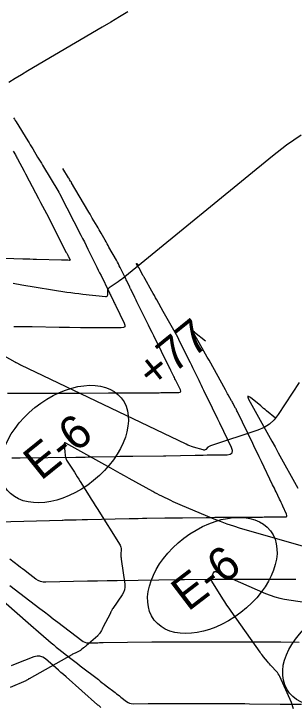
# Model space of a CAD drawing. Extents: x 1005228 to 1008882, y 1883389 to 1885754.
# Drawn here: x 1008004.6 to 1008057, y 1884530.7 to 1884660.1 of the extents above; entities that cross this region are included whole.
import ezdxf

# ---------------------------------------------------------------- set-up
doc = ezdxf.new("R2010")
doc.units = 0
for name, color, linetype in [('ATDIMS', 7, 'Continuous'), ('C-ANNO-NOTE', 7, 'Continuous'), ('R_Erosion', 7, 'Continuous'), ('S_BASELINE', 7, 'Continuous'), ('S_BRIDGE', 7, 'Continuous'), ('TSOBSTACLE', 7, 'Continuous')]:
    doc.layers.add(name, color=color, linetype=linetype)

msp = doc.modelspace()

# ---------------------------------------------------------------- linework, layer by layer
at = {"layer": 'ATDIMS'}
msp.add_lwpolyline([(1008001.59, 1884565.28), (1008013.61, 1884565.59), (1008013.83, 1884565.59), (1008014.05, 1884565.6), (1008014.27, 1884565.6), (1008014.49, 1884565.61), (1008015.36, 1884565.63), (1008015.58, 1884565.63), (1008015.79, 1884565.64), (1008016.01, 1884565.64), (1008016.23, 1884565.65), (1008017.35, 1884565.67), (1008017.61, 1884565.67), (1008017.87, 1884565.68), (1008018.13, 1884565.68), (1008018.39, 1884565.69), (1008026.17, 1884565.86), (1008027, 1884565.87), (1008027.83, 1884565.89), (1008028.66, 1884565.91), (1008029.49, 1884565.92), (1008032.81, 1884565.98), (1008033.63, 1884565.99), (1008034.46, 1884566.01), (1008035.29, 1884566.02), (1008036.12, 1884566.03), (1008040.57, 1884566.08), (1008041.1, 1884566.08), (1008041.63, 1884566.09), (1008042.16, 1884566.1), (1008042.68, 1884566.1), (1008044.79, 1884566.12), (1008045.32, 1884566.13), (1008045.85, 1884566.13), (1008046.38, 1884566.14), (1008046.9, 1884566.14), (1008050.49, 1884566.15), (1008050.8, 1884566.15), (1008051.11, 1884566.15), (1008051.43, 1884566.16), (1008051.74, 1884566.16), (1008053.04, 1884566.16), (1008053.32, 1884566.16), (1008053.6, 1884566.16), (1008053.88, 1884566.16), (1008054.15, 1884566.16), (1008055.26, 1884566.16), (1008055.49, 1884566.19), (1008055.62, 1884566.28), (1008055.66, 1884566.44), (1008055.59, 1884566.66), (1008054.92, 1884568.17), (1008054.76, 1884568.51), (1008054.61, 1884568.84), (1008054.45, 1884569.18), (1008054.29, 1884569.51), (1008053.64, 1884570.86), (1008053.48, 1884571.19), (1008053.32, 1884571.53), (1008053.15, 1884571.86), (1008052.99, 1884572.19), (1008050.89, 1884576.53), (1008050.49, 1884577.37), (1008050.09, 1884578.2), (1008049.68, 1884579.03), (1008049.28, 1884579.87), (1008046.4, 1884585.82), (1008046.32, 1884585.99), (1008046.23, 1884586.17), (1008046.14, 1884586.34), (1008046.04, 1884586.51), (1008045.67, 1884587.19), (1008045.58, 1884587.36), (1008045.48, 1884587.53), (1008045.39, 1884587.7), (1008045.29, 1884587.87), (1008044.7, 1884588.94), (1008044.57, 1884589.17), (1008044.44, 1884589.41), (1008044.31, 1884589.64), (1008044.18, 1884589.88), (1008041.09, 1884595.44), (1008040.77, 1884596), (1008040.46, 1884596.57), (1008040.14, 1884597.13), (1008039.82, 1884597.7), (1008037.97, 1884600.98), (1008037.95, 1884601.02), (1008037.95, 1884601.04), (1008037.96, 1884601.03), (1008038, 1884601.01), (1008038.2, 1884600.85), (1008038.3, 1884600.77), (1008038.39, 1884600.69), (1008040.42, 1884599.03)], dxfattribs=at)
at = {"layer": 'C-ANNO-NOTE'}
for points in [[(1008025.94, 1884660.48), (1008024.33, 1884659.53), (1008022.72, 1884658.58), (1008021.11, 1884657.63), (1008007.2, 1884649.44), (1008006.01, 1884648.73), (1008004.82, 1884648.02), (1008003.64, 1884647.29)], [(1008058.3, 1884637.44), (1008055.58, 1884635.56), (1008052.96, 1884633.54), (1008025.37, 1884611.02), (1008025.06, 1884610.77), (1008024.74, 1884610.53), (1008024.42, 1884610.3), (1008024.1, 1884610.07), (1008022.44, 1884608.93), (1008022.3, 1884608.81), (1008022.2, 1884608.68), (1008022.14, 1884608.52), (1008022.12, 1884608.34), (1008022.09, 1884607.59), (1008022.06, 1884607.43), (1008021.99, 1884607.32), (1008021.87, 1884607.26), (1008021.71, 1884607.26), (1008017.53, 1884607.71), (1008016.78, 1884607.8), (1008016.02, 1884607.9), (1008015.27, 1884608), (1008014.51, 1884608.11), (1008006.09, 1884609.43), (1008004.45, 1884609.75)], [(1008057.96, 1884591.26), (1008054.03, 1884585.3), (1008053.27, 1884584.33), (1008052.39, 1884583.52), (1008051.38, 1884582.88), (1008050.24, 1884582.4), (1008041.36, 1884579.46), (1008041.23, 1884579.41), (1008041.11, 1884579.34), (1008040.99, 1884579.26), (1008040.89, 1884579.17), (1008040.48, 1884578.79), (1008040.37, 1884578.71), (1008040.25, 1884578.66), (1008040.13, 1884578.65), (1008040, 1884578.67), (1008038.18, 1884579.21), (1008037.83, 1884579.32), (1008037.49, 1884579.45), (1008037.16, 1884579.58), (1008036.83, 1884579.73), (1008005.93, 1884594.49), (1008005.9, 1884594.51), (1008005.87, 1884594.53), (1008005.83, 1884594.54), (1008005.8, 1884594.56), (1008005.63, 1884594.65), (1008005.62, 1884594.66), (1008005.61, 1884594.67), (1008005.6, 1884594.68), (1008005.58, 1884594.68), (1008005.48, 1884594.74), (1008005.12, 1884594.93), (1008005.05, 1884594.96), (1008004.99, 1884595), (1008004.93, 1884595.03), (1008004.86, 1884595.07), (1007990.38, 1884603.18)], [(1008061.61, 1884559.84), (1008046.98, 1884564.04), (1008045.73, 1884564.42), (1008044.49, 1884564.84), (1008043.26, 1884565.29), (1008042.05, 1884565.77), (1008035.67, 1884568.43), (1008035.24, 1884568.62), (1008034.81, 1884568.81), (1008034.38, 1884569.01), (1008033.95, 1884569.21), (1008032.25, 1884570.03), (1008031.83, 1884570.24), (1008031.41, 1884570.46), (1008030.99, 1884570.68), (1008030.58, 1884570.9), (1008026.19, 1884573.34), (1008025.32, 1884573.82), (1008024.45, 1884574.3), (1008023.58, 1884574.79), (1008022.71, 1884575.27), (1008014.29, 1884579.95), (1008014.17, 1884580), (1008014.08, 1884579.98), (1008014.03, 1884579.91), (1008014.03, 1884579.78), (1008014.08, 1884579.11), (1008014.09, 1884578.95), (1008014.1, 1884578.78), (1008014.12, 1884578.62), (1008014.13, 1884578.45), (1008014.21, 1884577.55), (1008014.24, 1884577.35), (1008014.3, 1884577.15), (1008014.37, 1884576.97), (1008014.47, 1884576.79), (1008015.91, 1884574.53), (1008016.18, 1884574.09), (1008016.46, 1884573.66), (1008016.73, 1884573.22), (1008017.01, 1884572.79), (1008018.71, 1884570.11), (1008019.08, 1884569.52), (1008019.46, 1884568.93), (1008019.83, 1884568.33), (1008020.2, 1884567.74), (1008024.45, 1884560.91), (1008024.55, 1884560.72), (1008024.62, 1884560.51), (1008024.66, 1884560.3), (1008024.66, 1884560.09), (1008024.63, 1884559.19), (1008024.62, 1884558.97), (1008024.63, 1884558.75), (1008024.65, 1884558.53), (1008024.67, 1884558.31), (1008025.33, 1884553.6), (1008025.36, 1884553.07), (1008025.29, 1884552.57), (1008025.13, 1884552.08), (1008024.86, 1884551.62), (1008023.1, 1884549.06), (1008023.05, 1884549), (1008023.01, 1884548.93), (1008022.97, 1884548.86), (1008022.94, 1884548.79), (1008022.8, 1884548.51), (1008022.76, 1884548.44), (1008022.73, 1884548.37), (1008022.69, 1884548.3), (1008022.66, 1884548.23), (1008021.25, 1884545.51), (1008021.18, 1884545.37), (1008021.11, 1884545.24), (1008021.04, 1884545.11), (1008020.96, 1884544.97), (1008020.66, 1884544.45), (1008020.58, 1884544.32), (1008020.49, 1884544.2), (1008020.39, 1884544.09), (1008020.28, 1884543.98), (1008018.1, 1884542.09), (1008017.99, 1884542), (1008017.87, 1884541.9), (1008017.76, 1884541.81), (1008017.64, 1884541.71), (1008017.18, 1884541.34), (1008017.06, 1884541.25), (1008016.94, 1884541.16), (1008016.81, 1884541.09), (1008016.68, 1884541.03), (1008016.04, 1884540.74), (1008015.89, 1884540.67), (1008015.74, 1884540.6), (1008015.59, 1884540.52), (1008015.44, 1884540.44), (1008007.48, 1884535.97), (1008007.43, 1884535.94), (1008007.37, 1884535.91), (1008007.31, 1884535.87), (1008007.26, 1884535.84), (1008006.92, 1884535.63), (1008006.91, 1884535.63), (1008006.89, 1884535.62), (1008006.88, 1884535.61), (1008006.88, 1884535.61), (1008006.84, 1884535.59), (1008006.83, 1884535.58), (1008003.9, 1884534.33)]]:
    msp.add_lwpolyline(points, dxfattribs=at)
at = {"layer": 'R_Erosion'}
for centre, major_axis in [((1008014.03, 1884579.78), (10.66, 8.6)), ((1008041.71, 1884555.25), (10.87, 8.33)), ((1008067.49, 1884540.89), (11.85, 6.86))]:
    msp.add_ellipse(centre, major_axis=major_axis, ratio=0.638788, dxfattribs=at)
at = {"layer": 'S_BRIDGE'}
msp.add_lwpolyline([(1008056.87, 1884530.33), (1008056.77, 1884530.74), (1008056.65, 1884531.15), (1008056.49, 1884531.55), (1008054.35, 1884536.35), (1008054.21, 1884536.63), (1008054.05, 1884536.89), (1008053.87, 1884537.14), (1008053.66, 1884537.37), (1008052.75, 1884538.31), (1008052.56, 1884538.52), (1008052.37, 1884538.72), (1008052.19, 1884538.94), (1008052.01, 1884539.15), (1008051.3, 1884540.02), (1008051.13, 1884540.24), (1008050.96, 1884540.46), (1008050.79, 1884540.68), (1008050.63, 1884540.91), (1008045.23, 1884548.55), (1008044.83, 1884549.13), (1008044.44, 1884549.71), (1008044.05, 1884550.3), (1008043.67, 1884550.89), (1008041.61, 1884554.18), (1008041.54, 1884554.32), (1008041.5, 1884554.47), (1008041.51, 1884554.62), (1008041.54, 1884554.78), (1008041.85, 1884555.62), (1008041.87, 1884555.68), (1008041.9, 1884555.72), (1008041.93, 1884555.77), (1008041.97, 1884555.81), (1008042.13, 1884555.97), (1008042.17, 1884556), (1008042.21, 1884556.01), (1008042.26, 1884556.01), (1008042.31, 1884556), (1008051.65, 1884551.9), (1008052.52, 1884551.55), (1008053.41, 1884551.26), (1008054.31, 1884551.02), (1008055.23, 1884550.84), (1008058.95, 1884550.25)], dxfattribs=at)
at = {"layer": 'TSOBSTACLE'}
for points in [[(1008004.56, 1884640.67), (1008004.71, 1884640.42), (1008004.86, 1884640.18), (1008005.01, 1884639.94), (1008007.21, 1884636.39), (1008007.44, 1884636.02), (1008007.67, 1884635.64), (1008007.9, 1884635.26), (1008008.13, 1884634.88), (1008009.05, 1884633.36), (1008009.28, 1884632.98), (1008009.51, 1884632.6), (1008009.74, 1884632.22), (1008009.97, 1884631.84), (1008013, 1884626.82), (1008013.02, 1884626.79), (1008013.03, 1884626.77), (1008013.09, 1884626.67), (1008013.16, 1884626.55), (1008013.17, 1884626.53), (1008013.18, 1884626.51), (1008013.2, 1884626.48), (1008013.21, 1884626.46), (1008017.13, 1884618.81), (1008017.46, 1884618.16), (1008017.79, 1884617.51), (1008018.12, 1884616.85), (1008018.45, 1884616.2), (1008019.88, 1884613.29), (1008020.13, 1884612.78), (1008020.39, 1884612.26), (1008020.64, 1884611.74), (1008020.9, 1884611.23), (1008022.36, 1884608.26), (1008022.39, 1884608.2), (1008022.43, 1884608.14), (1008022.46, 1884608.07), (1008022.49, 1884608.01), (1008022.64, 1884607.68), (1008022.74, 1884607.49), (1008023.22, 1884606.49), (1008023.31, 1884606.3), (1008023.4, 1884606.11), (1008023.49, 1884605.92), (1008023.58, 1884605.73), (1008025.25, 1884602.35), (1008025.38, 1884601.96), (1008025.33, 1884601.69), (1008025.1, 1884601.52), (1008024.69, 1884601.47), (1008022.68, 1884601.49), (1008022.2, 1884601.49), (1008021.71, 1884601.49), (1008021.22, 1884601.5), (1008020.73, 1884601.5), (1008018.54, 1884601.5), (1008018.17, 1884601.5), (1008017.81, 1884601.5), (1008017.44, 1884601.51), (1008017.08, 1884601.51), (1008015, 1884601.53), (1008014.95, 1884601.53), (1008014.89, 1884601.53), (1008014.83, 1884601.53), (1008014.78, 1884601.53), (1008014.55, 1884601.53), (1008014.5, 1884601.54), (1008014.44, 1884601.54), (1008014.38, 1884601.54), (1008014.33, 1884601.54), (1008013.9, 1884601.55), (1008013.83, 1884601.55), (1008013.76, 1884601.55), (1008013.7, 1884601.55), (1008013.63, 1884601.55), (1008013.36, 1884601.55), (1008013.29, 1884601.56), (1008013.22, 1884601.56), (1008013.15, 1884601.56), (1008013.09, 1884601.56), (1008008.04, 1884601.64), (1008007.18, 1884601.66), (1008006.31, 1884601.67), (1008005.45, 1884601.68), (1008004.59, 1884601.69)], [(1008004.5, 1884634.47), (1008004.89, 1884633.76), (1008004.99, 1884633.59), (1008005.08, 1884633.41), (1008005.18, 1884633.23), (1008005.28, 1884633.05), (1008006.52, 1884630.71), (1008006.76, 1884630.26), (1008007, 1884629.81), (1008007.24, 1884629.36), (1008007.48, 1884628.91), (1008009.24, 1884625.61), (1008009.61, 1884624.91), (1008009.98, 1884624.21), (1008010.34, 1884623.51), (1008010.7, 1884622.8), (1008014.41, 1884615.57), (1008014.48, 1884615.44), (1008014.54, 1884615.32), (1008014.67, 1884615.06), (1008014.7, 1884615), (1008014.73, 1884614.94), (1008014.76, 1884614.88), (1008014.8, 1884614.81), (1008015.09, 1884614.22), (1008015.11, 1884614.16), (1008015.1, 1884614.12), (1008015.06, 1884614.09), (1008015, 1884614.08), (1008014.68, 1884614.09), (1008014.6, 1884614.09), (1008014.52, 1884614.09), (1008014.44, 1884614.09), (1008014.36, 1884614.09), (1008013.93, 1884614.1), (1008013.83, 1884614.1), (1008013.74, 1884614.1), (1008013.64, 1884614.11), (1008013.54, 1884614.11), (1008008.86, 1884614.25), (1008008.22, 1884614.27), (1008007.58, 1884614.29), (1008006.94, 1884614.31), (1008006.3, 1884614.33), (1008002.92, 1884614.41)], [(1008003.44, 1884589.28), (1008005.09, 1884589.29), (1008005.45, 1884589.29), (1008005.8, 1884589.29), (1008006.16, 1884589.29), (1008006.51, 1884589.29), (1008013.79, 1884589.28), (1008014.58, 1884589.28), (1008015.36, 1884589.29), (1008016.15, 1884589.29), (1008016.94, 1884589.29), (1008022.31, 1884589.34), (1008022.76, 1884589.34), (1008023.21, 1884589.34), (1008023.65, 1884589.35), (1008024.1, 1884589.35), (1008025.89, 1884589.36), (1008026.33, 1884589.36), (1008026.78, 1884589.37), (1008027.23, 1884589.37), (1008027.67, 1884589.37), (1008030.87, 1884589.37), (1008031.18, 1884589.37), (1008031.49, 1884589.37), (1008031.8, 1884589.37), (1008032.11, 1884589.38), (1008033.46, 1884589.4), (1008033.71, 1884589.4), (1008033.96, 1884589.41), (1008034.21, 1884589.41), (1008034.46, 1884589.41), (1008035.47, 1884589.42), (1008035.67, 1884589.45), (1008035.79, 1884589.54), (1008035.81, 1884589.68), (1008035.75, 1884589.88), (1008034.95, 1884591.53), (1008034.84, 1884591.75), (1008034.73, 1884591.97), (1008034.62, 1884592.19), (1008034.52, 1884592.41), (1008034.08, 1884593.28), (1008033.97, 1884593.5), (1008033.87, 1884593.72), (1008033.76, 1884593.93), (1008033.65, 1884594.15), (1008030.77, 1884599.97), (1008030.44, 1884600.63), (1008030.11, 1884601.3), (1008029.78, 1884601.96), (1008029.45, 1884602.63), (1008027.74, 1884606.11), (1008027.61, 1884606.36), (1008027.49, 1884606.62), (1008027.36, 1884606.87), (1008027.24, 1884607.13), (1008026.53, 1884608.56), (1008026.51, 1884608.61), (1008026.49, 1884608.65), (1008026.47, 1884608.7), (1008026.44, 1884608.74), (1008026.31, 1884609.01), (1008026.27, 1884609.1), (1008025.71, 1884610.27), (1008025.61, 1884610.47), (1008025.51, 1884610.68), (1008025.41, 1884610.89), (1008025.3, 1884611.1), (1008024.49, 1884612.75), (1008024.32, 1884613.09), (1008024.14, 1884613.43), (1008023.96, 1884613.77), (1008023.77, 1884614.11), (1008022.39, 1884616.53), (1008022.21, 1884616.86), (1008022.02, 1884617.18), (1008021.84, 1884617.51), (1008021.65, 1884617.84), (1008020.91, 1884619.15), (1008020.72, 1884619.47), (1008020.53, 1884619.8), (1008020.34, 1884620.13), (1008020.16, 1884620.45), (1008019.27, 1884621.97), (1008019.06, 1884622.33), (1008018.85, 1884622.69), (1008018.63, 1884623.05), (1008018.42, 1884623.41), (1008015.39, 1884628.58), (1008015.35, 1884628.66), (1008015.3, 1884628.74), (1008015.25, 1884628.81), (1008015.21, 1884628.89), (1008015.02, 1884629.2), (1008014.93, 1884629.36), (1008014.83, 1884629.51), (1008013.78, 1884631.26)], [(1008004.2, 1884577.19), (1008004.73, 1884577.2), (1008005.27, 1884577.21), (1008005.8, 1884577.21), (1008016.2, 1884577.32), (1008016.35, 1884577.33), (1008016.5, 1884577.33), (1008016.65, 1884577.33), (1008016.8, 1884577.33), (1008017.45, 1884577.35), (1008017.58, 1884577.35), (1008017.71, 1884577.36), (1008017.83, 1884577.36), (1008017.96, 1884577.36), (1008018.47, 1884577.37), (1008018.6, 1884577.37), (1008018.73, 1884577.37), (1008018.85, 1884577.38), (1008018.98, 1884577.38), (1008023.59, 1884577.48), (1008024.4, 1884577.49), (1008025.21, 1884577.51), (1008026.02, 1884577.52), (1008026.84, 1884577.53), (1008032.57, 1884577.61), (1008032.61, 1884577.61), (1008032.65, 1884577.61), (1008032.72, 1884577.61), (1008032.76, 1884577.61), (1008032.79, 1884577.61), (1008032.9, 1884577.61), (1008032.93, 1884577.61), (1008032.95, 1884577.61), (1008032.98, 1884577.61), (1008033, 1884577.61), (1008038.53, 1884577.71), (1008039.27, 1884577.72), (1008040.01, 1884577.73), (1008040.75, 1884577.74), (1008041.49, 1884577.75), (1008044.46, 1884577.78), (1008045.06, 1884577.87), (1008045.41, 1884578.13), (1008045.48, 1884578.55), (1008045.29, 1884579.13), (1008043.09, 1884583.69), (1008042.75, 1884584.4), (1008042.41, 1884585.1), (1008042.07, 1884585.81), (1008041.73, 1884586.51), (1008040.13, 1884589.79), (1008039.9, 1884590.26), (1008039.67, 1884590.73), (1008039.45, 1884591.2), (1008039.22, 1884591.66), (1008038.31, 1884593.54), (1008038.08, 1884594), (1008037.85, 1884594.47), (1008037.62, 1884594.94), (1008037.39, 1884595.41), (1008035.46, 1884599.28), (1008035.24, 1884599.73), (1008035.01, 1884600.18), (1008034.77, 1884600.62), (1008034.52, 1884601.06), (1008033.53, 1884602.81), (1008033.29, 1884603.25), (1008033.04, 1884603.68), (1008032.79, 1884604.12), (1008032.54, 1884604.56), (1008031.34, 1884606.7), (1008031.11, 1884607.1), (1008030.88, 1884607.51), (1008030.65, 1884607.91), (1008030.42, 1884608.32), (1008029.1, 1884610.67), (1008029.07, 1884610.71), (1008029.05, 1884610.76), (1008029.02, 1884610.81), (1008029, 1884610.85), (1008028.89, 1884611.03), (1008028.84, 1884611.12), (1008028.79, 1884611.21), (1008028.01, 1884612.63), (1008027.98, 1884612.67), (1008027.96, 1884612.71), (1008027.94, 1884612.75), (1008027.91, 1884612.79), (1008027.8, 1884613), (1008027.73, 1884613.12), (1008027.55, 1884613.44), (1008027.52, 1884613.49), (1008027.52, 1884613.51), (1008027.54, 1884613.5), (1008027.59, 1884613.47), (1008027.95, 1884613.15)], [(1008053.53, 1884584.63), (1008051.86, 1884585.99), (1008051.58, 1884586.21), (1008051.3, 1884586.44), (1008051.03, 1884586.66), (1008050.75, 1884586.89), (1008048.82, 1884588.45), (1008048.48, 1884588.69), (1008048.32, 1884588.72), (1008048.33, 1884588.56), (1008048.5, 1884588.19), (1008051.61, 1884582.53), (1008052.22, 1884581.44), (1008052.82, 1884580.34), (1008053.43, 1884579.24), (1008054.03, 1884578.14), (1008057.67, 1884571.52)], [(1008057.33, 1884554.48), (1008056.79, 1884554.48), (1008056.25, 1884554.48), (1008052.76, 1884554.49), (1008052.63, 1884554.49), (1008052.5, 1884554.49), (1008052.36, 1884554.49), (1008052.23, 1884554.49), (1008051.65, 1884554.49), (1008051.54, 1884554.49), (1008051.43, 1884554.49), (1008051.32, 1884554.49), (1008051.21, 1884554.49), (1008050.76, 1884554.49), (1008050.65, 1884554.49), (1008050.54, 1884554.49), (1008050.42, 1884554.49), (1008050.31, 1884554.49), (1008045.53, 1884554.49), (1008044.7, 1884554.49), (1008043.86, 1884554.49), (1008043.03, 1884554.48), (1008042.19, 1884554.48), (1008036.52, 1884554.43), (1008036.09, 1884554.43), (1008035.98, 1884554.43), (1008035.87, 1884554.43), (1008035.76, 1884554.43), (1008035.65, 1884554.42), (1008023.89, 1884554.26), (1008023.43, 1884554.25), (1008022.97, 1884554.24), (1008022.52, 1884554.24), (1008022.06, 1884554.23), (1008020.22, 1884554.19), (1008019.76, 1884554.19), (1008019.31, 1884554.18), (1008018.85, 1884554.17), (1008018.39, 1884554.15), (1008010.57, 1884553.96), (1008010.06, 1884553.99), (1008009.58, 1884554.1), (1008009.13, 1884554.29), (1008008.71, 1884554.57), (1008007.02, 1884555.86), (1008006.63, 1884556.16), (1008006.24, 1884556.46), (1008005.84, 1884556.76), (1008005.45, 1884557.07), (1008003.88, 1884558.28)], [(1008003.88, 1884553.38), (1008009.47, 1884549.1), (1008010.31, 1884548.45), (1008011.15, 1884547.81), (1008011.98, 1884547.16), (1008012.82, 1884546.52), (1008017.29, 1884543.08), (1008017.58, 1884542.89), (1008017.88, 1884542.76), (1008018.2, 1884542.68), (1008018.54, 1884542.66), (1008019.93, 1884542.69), (1008020.28, 1884542.69), (1008020.63, 1884542.7), (1008020.97, 1884542.7), (1008021.32, 1884542.71), (1008030.4, 1884542.82), (1008031.08, 1884542.82), (1008031.76, 1884542.83), (1008032.43, 1884542.84), (1008033.11, 1884542.84), (1008035.82, 1884542.86), (1008036.5, 1884542.87), (1008037.17, 1884542.87), (1008037.85, 1884542.87), (1008038.53, 1884542.87), (1008045.34, 1884542.88), (1008045.43, 1884542.88), (1008045.53, 1884542.88), (1008045.62, 1884542.88), (1008045.71, 1884542.88), (1008046.09, 1884542.88), (1008046.18, 1884542.88), (1008046.27, 1884542.88), (1008046.37, 1884542.88), (1008046.46, 1884542.88), (1008050.13, 1884542.87), (1008050.5, 1884542.87), (1008050.86, 1884542.87), (1008051.22, 1884542.87), (1008051.59, 1884542.87), (1008053.04, 1884542.86), (1008053.41, 1884542.85), (1008053.77, 1884542.85), (1008054.14, 1884542.85), (1008054.5, 1884542.84), (1008057.93, 1884542.81)], [(1008001.05, 1884551.79), (1008007.3, 1884546.37), (1008007.77, 1884545.96), (1008008.25, 1884545.55), (1008008.72, 1884545.13), (1008009.19, 1884544.72), (1008011.09, 1884543.07), (1008011.56, 1884542.66), (1008012.05, 1884542.26), (1008012.53, 1884541.86), (1008013.03, 1884541.47), (1008015.03, 1884539.93), (1008015.53, 1884539.55), (1008016.03, 1884539.17), (1008016.53, 1884538.78), (1008017.03, 1884538.39), (1008020.4, 1884535.79), (1008020.77, 1884535.5), (1008021.14, 1884535.22), (1008021.51, 1884534.93), (1008021.87, 1884534.65), (1008023.55, 1884533.36), (1008023.81, 1884533.15), (1008024.08, 1884532.94), (1008024.35, 1884532.74), (1008024.61, 1884532.53), (1008025.68, 1884531.7), (1008025.96, 1884531.52), (1008026.25, 1884531.39), (1008026.56, 1884531.32), (1008026.89, 1884531.29), (1008029.73, 1884531.31), (1008030.32, 1884531.31), (1008030.9, 1884531.32), (1008031.49, 1884531.32), (1008032.07, 1884531.32), (1008035.53, 1884531.33), (1008035.82, 1884531.33), (1008036.1, 1884531.33), (1008036.38, 1884531.33), (1008036.67, 1884531.33), (1008037.85, 1884531.34), (1008038.11, 1884531.34), (1008038.37, 1884531.34), (1008038.62, 1884531.34), (1008038.88, 1884531.34), (1008039.91, 1884531.34), (1008040.17, 1884531.33), (1008040.43, 1884531.33), (1008040.69, 1884531.33), (1008040.95, 1884531.33), (1008045.35, 1884531.32), (1008046.17, 1884531.32), (1008046.99, 1884531.32), (1008047.81, 1884531.31), (1008048.63, 1884531.3), (1008054.38, 1884531.24), (1008054.75, 1884531.24), (1008054.85, 1884531.24), (1008054.94, 1884531.24), (1008055.04, 1884531.23), (1008055.13, 1884531.23), (1008058.39, 1884531.18)], [(1008020.84, 1884530.61), (1008020.46, 1884530.94), (1008020.33, 1884531.05), (1008020.27, 1884531.11), (1008014.36, 1884536.3), (1008013.88, 1884536.72), (1008013.4, 1884537.14), (1008012.92, 1884537.56), (1008012.43, 1884537.98), (1008010.5, 1884539.67), (1008010.01, 1884540.01), (1008009.48, 1884540.18), (1008008.93, 1884540.19), (1008008.35, 1884540.04), (1008004.85, 1884538.65), (1008004.07, 1884538.34)]]:
    msp.add_lwpolyline(points, dxfattribs=at)

# ---------------------------------------------------------------- texts
at = {"layer": 'R_Erosion'}
for rotation, p in [(38.9079, (1008009.66, 1884572.83)), (37.4532, (1008037.17, 1884548.41))]:
    msp.add_text('E-6', height=6.25, rotation=rotation, dxfattribs=at).set_placement(p)
at = {"layer": 'S_BASELINE'}
msp.add_text('+77', height=6.25, rotation=38.9079, dxfattribs=at).set_placement((1008030.73, 1884589.84))

doc.saveas('drawing.dxf')
